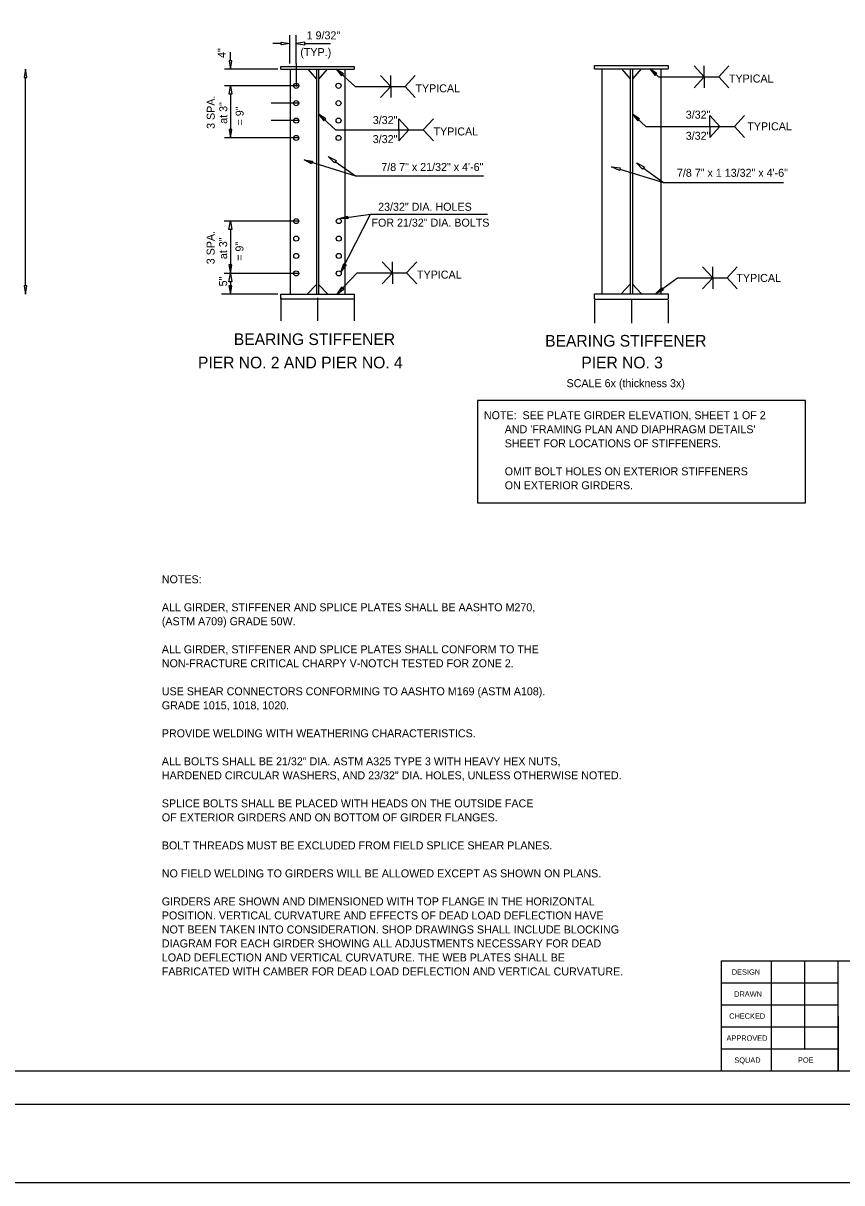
# Model space of a CAD drawing. Extents: x 4944 to 17449, y 3824 to 49087.
# Drawn here: x 12253 to 13431, y 8315 to 9984 of the extents above; entities that cross this region are included whole.
import ezdxf

# ---------------------------------------------------------------- set-up
doc = ezdxf.new("R2010")
doc.units = 0
for name, color, linetype in [('36_S_LINES', 7, 'Continuous'), ('37_S_TXT', 7, 'Continuous'), ('3A', 7, 'Continuous'), ('BEAM', 7, 'Continuous'), ('DIM', 7, 'Continuous'), ('Level 14', 7, 'Continuous'), ('Level 17', 7, 'Continuous'), ('Level 25', 7, 'Continuous'), ('REVISED', 7, 'Continuous')]:
    doc.layers.add(name, color=color, linetype=linetype)

msp = doc.modelspace()

# ---------------------------------------------------------------- linework, layer by layer
at = {"layer": '36_S_LINES'}
for p, q in [((12636.4, 9926.3), (12636.4, 9967.1)), ((12624.2, 9954.8), (12612, 9954.8)), ((12658, 9954.8), (12695, 9954.8)), ((12551.1, 9930.2), (12551.1, 9942.4)), ((12619.1, 9918.1), (12542.4, 9918.1)), ((12703.3, 9918), (12730.6, 9892.9)), ((13154.8, 9918.6), (13167.3, 9907)), ((13218.6, 9922.8), (13233.2, 9907)), ((13233.2, 9906.8), (13233.2, 9922.8)), ((13268.5, 9922.8), (13253.9, 9907)), ((12767.1, 9908.8), (12781.8, 9892.9)), ((12781.8, 9892.8), (12781.8, 9908.8)), ((12817.1, 9908.8), (12802.4, 9892.9)), ((13167.3, 9907), (13253.9, 9907)), ((13218.6, 9891.1), (13233.2, 9907)), ((13233.2, 9907.1), (13233.2, 9891.1)), ((13268.5, 9891.1), (13253.9, 9907)), ((12551.1, 9882), (12551.1, 9819)), ((12730.6, 9892.9), (12802.4, 9892.9)), ((12767.1, 9877.1), (12781.8, 9892.9)), ((12781.8, 9893.1), (12781.8, 9877.1)), ((12817.1, 9877.1), (12802.4, 9892.9)), ((12677.9, 9853.4), (12702.3, 9830.9)), ((12793.2, 9830.7), (12793.2, 9846.7)), ((12793.2, 9846.7), (12807.9, 9830.9)), ((12843.2, 9846.7), (12828.6, 9830.9)), ((13129.8, 9853.3), (13149, 9835.7)), ((13241.2, 9835.5), (13241.2, 9851.5)), ((13241.2, 9851.5), (13255.8, 9835.7)), ((13291.2, 9851.5), (13276.5, 9835.7)), ((12702.3, 9830.9), (12828.6, 9830.9)), ((12793.2, 9831), (12793.2, 9815)), ((12793.2, 9815), (12807.9, 9830.9)), ((12843.2, 9815), (12828.6, 9830.9)), ((13149, 9835.7), (13276.5, 9835.7)), ((13241.2, 9835.8), (13241.2, 9819.8)), ((13241.2, 9819.8), (13255.8, 9835.7)), ((13291.2, 9819.8), (13276.5, 9835.7)), ((12657, 9787.4), (12730.8, 9764.3)), ((12701.9, 9785.1), (12730.8, 9764.3)), ((12730.8, 9764.3), (12915.1, 9764.3)), ((13111.4, 9773.9), (13174.3, 9755.1)), ((13145.3, 9775.9), (13174.3, 9755.1)), ((13174.3, 9755.1), (13347.3, 9755.1)), ((12707.9, 9702.9), (12752.5, 9709.1)), ((12710.5, 9626.7), (12752.5, 9709.1)), ((12752.5, 9709.1), (12921.2, 9709.1)), ((12550.9, 9687.1), (12550.9, 9624.1)), ((12769.4, 9640.7), (12784.1, 9624.9)), ((12784.1, 9624.7), (12784.1, 9640.7)), ((12819.4, 9640.7), (12804.7, 9624.9)), ((13230.6, 9633.5), (13245.3, 9617.7)), ((13245.3, 9617.5), (13245.3, 9633.5)), ((13280.6, 9633.5), (13266, 9617.7)), ((12704, 9594.1), (12733.5, 9624.9)), ((12733.5, 9624.9), (12804.7, 9624.9)), ((12769.4, 9609), (12784.1, 9624.9)), ((12784.1, 9625), (12784.1, 9609)), ((12819.4, 9609), (12804.7, 9624.9)), ((13162.9, 9594.6), (13194.7, 9617.7)), ((13194.7, 9617.7), (13266, 9617.7)), ((13230.6, 9601.8), (13245.3, 9617.7)), ((13245.3, 9617.8), (13245.3, 9601.8)), ((13280.6, 9601.8), (13266, 9617.7)), ((12550.9, 9612), (12550.9, 9594.1)), ((12619.2, 9594.1), (12537.9, 9594.1))]:
    msp.add_line(p, q, dxfattribs=at)
for points in [[(12624.2, 9952.8), (12624.2, 9956.9), (12636.4, 9954.8)], [(12658, 9952.8), (12658, 9956.9), (12645.8, 9954.8)], [(12553.2, 9930.2), (12549.1, 9930.2), (12551.1, 9918.1)], [(12710.8, 9908.2), (12713.6, 9911.2), (12703.3, 9918)], [(13162.3, 9908.7), (13165.1, 9911.7), (13154.8, 9918.6)], [(12553.2, 9882), (12549.1, 9882), (12551.1, 9894.1)], [(12685.4, 9843.5), (12688.2, 9846.5), (12677.9, 9853.4)], [(13137.3, 9843.5), (13140.1, 9846.5), (13129.8, 9853.3)], [(12553.2, 9831.1), (12549.1, 9831.1), (12551.1, 9819)], [(12667.9, 9782), (12657, 9787.4), (12669.1, 9785.8)], [(12703.1, 9786.7), (12700.7, 9783.4), (12691.9, 9792.2)], [(13146.5, 9777.5), (13144.1, 9774.2), (13135.4, 9783)], [(13112, 9775.9), (13110.9, 9772), (13099.7, 9777.4)], [(12552.9, 9687.1), (12548.9, 9687.1), (12550.9, 9699.3)], [(12720.1, 9702.6), (12707.9, 9702.9), (12719.5, 9706.5)], [(12552.9, 9636.2), (12548.9, 9636.2), (12550.9, 9624.1)], [(12717.7, 9636.5), (12710.5, 9626.7), (12714.1, 9638.3)], [(12552.9, 9612), (12548.9, 9612), (12550.9, 9624.1)], [(12552.9, 9606.2), (12548.9, 9606.2), (12550.9, 9594.1)], [(12714, 9601.4), (12711.1, 9604.3), (12704, 9594.1)], [(13173.8, 9600), (13162.9, 9594.6), (13171.4, 9603.2)]]:
    msp.add_lwpolyline(points, close=True, dxfattribs=at)
at = {"layer": '37_S_TXT'}
msp.add_lwpolyline([(10619.3, 10619.3), (14075.4, 10619.3), (14075.4, 8315.3), (10619.3, 8315.3)], close=True, dxfattribs=at)
at = {"layer": '3A'}
for p, q in [((12645.8, 9926.3), (12645.8, 9967.1)), ((12623.6, 9894.1), (12542.4, 9894.1)), ((12623.6, 9819), (12542.4, 9819)), ((12623.4, 9699.3), (12542.1, 9699.3)), ((12623.4, 9624.1), (12542.1, 9624.1))]:
    msp.add_line(p, q, dxfattribs=at)
msp.add_lwpolyline([(12906.5, 9293.7), (13378.8, 9293.7), (13378.8, 9441.2), (12906.5, 9441.2)], close=True, dxfattribs=at)
at = {"layer": 'DEFPOINTS'}
for p, q in [((12645.8, 9926.3), (12645.8, 9893.1)), ((12256, 9606.1), (12256, 9906.1)), ((12648.8, 9894.1), (12609.8, 9894.1)), ((12648.8, 9869.1), (12609.8, 9869.1)), ((12648.8, 9844), (12609.8, 9844)), ((12648.8, 9819), (12609.8, 9819)), ((12648.6, 9699.3), (12609.6, 9699.3)), ((12648.6, 9624.1), (12609.6, 9624.1)), ((12623.3, 9588.9), (12623.3, 9555.9)), ((12676.3, 9588.9), (12676.3, 9555.9)), ((12729.3, 9588.9), (12729.3, 9555.9)), ((13075.3, 9585.6), (13075.3, 9552.6)), ((13128.3, 9585.6), (13128.3, 9552.6)), ((13181.3, 9585.6), (13181.3, 9552.6))]:
    msp.add_line(p, q, dxfattribs=at)
for points in [[(12258, 9906.1), (12256, 9918.1), (12254, 9906.1)], [(12254, 9606.1), (12256, 9594.1), (12258, 9606.1)]]:
    msp.add_lwpolyline(points, close=True, dxfattribs=at)
at = {"layer": 'DIM'}
msp.add_lwpolyline([(10776.5, 10540.1), (14040.6, 10540.1), (14040.6, 8428.1), (10776.5, 8428.1)], close=True, dxfattribs=at)
at = {"layer": 'Level 14'}
for p, q in [((13258.2, 8476.1), (13258.2, 8634.5)), ((13258.2, 8634.5), (13987.8, 8634.5)), ((13426.1, 8476.1), (13426.1, 8634.5)), ((13426.2, 8476.1), (13426.1, 8634.5))]:
    msp.add_line(p, q, dxfattribs=at)
msp.add_lwpolyline([(13987.8, 8476.1), (10963.7, 8476.1), (10963.7, 10492.1), (13987.8, 10492.1)], close=True, dxfattribs=at)
at = {"layer": 'Level 17'}
for p, q in [((13330.1, 8476.1), (13330.1, 8634.5)), ((13378.1, 8507.8), (13378.1, 8634.5))]:
    msp.add_line(p, q, dxfattribs=at)
for points in [[(13426.1, 8602.8), (13258.2, 8602.8)], [(13426.1, 8571.1), (13258.2, 8571.1)], [(13426.1, 8539.4), (13258.2, 8539.4)], [(13426.1, 8507.8), (13258.2, 8507.8)]]:
    msp.add_lwpolyline(points, dxfattribs=at)
at = {"layer": 'Level 25'}
for p, q in [((12623.3, 9921.9), (12729.3, 9921.9)), ((12623.3, 9918.1), (12623.3, 9921.9)), ((12623.3, 9918.1), (12729.3, 9918.1)), ((12636.8, 9918.1), (12636.8, 9594.1)), ((12662.4, 9918.1), (12674.8, 9903.7)), ((12674.8, 9918.1), (12674.8, 9594.1)), ((12677.9, 9918.1), (12677.9, 9594.1)), ((12690.3, 9918.1), (12677.9, 9903.7)), ((12715.9, 9918.1), (12715.9, 9594.1)), ((12729.3, 9921.9), (12729.3, 9918.1)), ((13075.3, 9923.1), (13181.3, 9923.1)), ((13075.3, 9918.6), (13075.3, 9923.1)), ((13075.3, 9918.6), (13181.3, 9918.6)), ((13085.7, 9918.6), (13085.7, 9594.6)), ((13114.2, 9918.6), (13126.7, 9904.1)), ((13126.7, 9918.6), (13126.7, 9594.6)), ((13129.8, 9918.6), (13129.8, 9594.6)), ((13142.3, 9918.6), (13129.8, 9904.1)), ((13170.8, 9918.6), (13170.8, 9594.6)), ((13181.3, 9923.1), (13181.3, 9918.6)), ((12661.6, 9594.1), (12674.8, 9608.3)), ((12691, 9594.1), (12677.9, 9608.3)), ((13113.5, 9594.6), (13126.7, 9608.8)), ((13143, 9594.6), (13129.8, 9608.8)), ((12623.3, 9594.1), (12729.3, 9594.1)), ((12623.3, 9587.7), (12623.3, 9594.1)), ((12623.3, 9587.7), (12729.3, 9587.7)), ((12729.3, 9594.1), (12729.3, 9587.7)), ((13075.3, 9594.6), (13181.3, 9594.6)), ((13075.3, 9587.1), (13075.3, 9594.6)), ((13075.3, 9587.1), (13181.3, 9587.1)), ((13181.3, 9594.6), (13181.3, 9587.1))]:
    msp.add_line(p, q, dxfattribs=at)
for centre, radius in [((12645.8, 9894.1), 3.67), ((12706.6, 9894.1), 3.67), ((12645.8, 9869.1), 3.62), ((12706.6, 9869.1), 3.62), ((12645.8, 9844), 3.62), ((12706.6, 9844), 3.62), ((12645.8, 9819), 3.62), ((12706.6, 9819), 3.62), ((12645.8, 9699.3), 3.62), ((12706.9, 9699.3), 3.62), ((12645.8, 9674.2), 3.62), ((12706.9, 9674.2), 3.62), ((12645.8, 9649.2), 3.62), ((12706.9, 9649.2), 3.62), ((12645.8, 9624.1), 3.62), ((12706.9, 9624.1), 3.62)]:
    msp.add_circle(centre, radius, dxfattribs=at)

# ---------------------------------------------------------------- texts
at = {"layer": '3A'}
for s, p in [('1 9/32"', (12660.7, 9960.9)), ('(TYP.)', (12651.6, 9936.8)), ('TYPICAL', (13268.7, 9898.8)), ('TYPICAL', (12817.3, 9884.7)), ('3/32"', (12755.9, 9839)), ('3/32"', (13206.5, 9846.8)), ('TYPICAL', (12843.4, 9822.6)), ('TYPICAL', (13295.1, 9830)), ('3/32"', (12755.9, 9811.6)), ('3/32"', (13206.5, 9816.4)), ('7/8 7" x 21/32" x 4\'-6"', (12768.2, 9771.5)), ('7/8 7" x 1 13/32" x 4\'-6"', (13193.8, 9763.1)), ('23/32" DIA. HOLES', (12763.6, 9714.2)), ('FOR 21/32" DIA. BOLTS', (12754, 9691.4)), ('TYPICAL', (12819.6, 9616.6)), ('TYPICAL', (13279.4, 9611.8)), ('NOTE:  SEE PLATE GIRDER ELEVATION, SHEET 1 OF 2 ', (12915.9, 9414.2)), ("       AND 'FRAMING PLAN AND DIAPHRAGM DETAILS' ", (12915.9, 9394)), ('       SHEET FOR LOCATIONS OF STIFFENERS. ', (12915.9, 9373.8)), ('       OMIT BOLT HOLES ON EXTERIOR STIFFENERS ', (12915.9, 9333.5)), ('       ON EXTERIOR GIRDERS.', (12915.9, 9313.4)), ('NOTES:', (12452.2, 9178.1)), ('ALL GIRDER, STIFFENER AND SPLICE PLATES SHALL BE AASHTO M270,', (12452.2, 9137.8)), ('(ASTM A709) GRADE 50W.', (12452.2, 9117.7)), ('ALL GIRDER, STIFFENER AND SPLICE PLATES SHALL CONFORM TO THE', (12452.2, 9077.3)), ('NON-FRACTURE CRITICAL CHARPY V-NOTCH TESTED FOR ZONE 2.', (12452.2, 9057.2)), ('USE SHEAR CONNECTORS CONFORMING TO AASHTO M169 (ASTM A108).', (12452.2, 9016.9)), ('GRADE 1015, 1018, 1020.', (12452.2, 8996.7)), ('PROVIDE WELDING WITH WEATHERING CHARACTERISTICS.  ', (12452.2, 8956.4)), ('ALL BOLTS SHALL BE 21/32" DIA. ASTM A325 TYPE 3 WITH HEAVY HEX NUTS, ', (12452.2, 8916.1)), ('HARDENED CIRCULAR WASHERS, AND 23/32" DIA. HOLES, UNLESS OTHERWISE NOTED.  ', (12452.2, 8895.9)), ('SPLICE BOLTS SHALL BE PLACED WITH HEADS ON THE OUTSIDE FACE', (12452.2, 8855.6)), ('OF EXTERIOR GIRDERS AND ON BOTTOM OF GIRDER FLANGES.  ', (12452.2, 8835.4)), ('BOLT THREADS MUST BE EXCLUDED FROM FIELD SPLICE SHEAR PLANES.', (12452.2, 8795.1)), ('NO FIELD WELDING TO GIRDERS WILL BE ALLOWED EXCEPT AS SHOWN ON PLANS.', (12452.2, 8754.8)), ('GIRDERS ARE SHOWN AND DIMENSIONED WITH TOP FLANGE IN THE HORIZONTAL', (12452.2, 8714.5)), ('POSITION. VERTICAL CURVATURE AND EFFECTS OF DEAD LOAD DEFLECTION HAVE ', (12452.2, 8694.3)), ('NOT BEEN TAKEN INTO CONSIDERATION. SHOP DRAWINGS SHALL INCLUDE BLOCKING ', (12452.2, 8674.1)), ('DIAGRAM FOR EACH GIRDER SHOWING ALL ADJUSTMENTS NECESSARY FOR DEAD ', (12452.2, 8654)), ('LOAD DEFLECTION AND VERTICAL CURVATURE. THE WEB PLATES SHALL BE ', (12452.2, 8633.8)), ('FABRICATED WITH CAMBER FOR DEAD LOAD DEFLECTION AND VERTICAL CURVATURE.', (12452.2, 8613.7))]:
    msp.add_text(s, height=11.52, dxfattribs=at).set_placement(p)
for s, p in [('4"', (12544.2, 9934.1)), ('3 SPA.', (12528.4, 9832)), ('at 3"', (12546.4, 9839.4)), ('= 9"', (12570, 9837)), ('3 SPA.', (12528.2, 9637.2)), ('at 3"', (12546.2, 9644.6)), ('= 9"', (12569.7, 9642.2)), ('5"', (12546.2, 9605.4))]:
    msp.add_text(s, height=11.52, rotation=90, dxfattribs=at).set_placement(p)
at = {"layer": 'BEAM'}
for s, p in [('BEARING STIFFENER', (12555.9, 9521)), ('BEARING STIFFENER', (13004.1, 9518.7)), ('PIER NO. 2 AND PIER NO. 4', (12504.3, 9487.4)), ('PIER NO. 3', (13056.2, 9487.4))]:
    msp.add_text(s, height=16.8, dxfattribs=at).set_placement(p)
at = {"layer": 'DEFPOINTS'}
msp.add_text('SCALE 6x (thickness 3x)', height=11.52, dxfattribs=at).set_placement((13034.9, 9460.3))
at = {"layer": 'REVISED'}
for s, p in [('DESIGN', (13272.8, 8614.8)), ('DRAWN', (13276.2, 8583.1)), ('CHECKED', (13269, 8551.4)), ('APPROVED', (13265.2, 8519.7)), ('SQUAD', (13276.5, 8488)), ('POE', (13368.1, 8488.1))]:
    msp.add_text(s, height=7.68, dxfattribs=at).set_placement(p)

doc.saveas('drawing.dxf')
